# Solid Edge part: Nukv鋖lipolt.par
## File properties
Author: Türk
Template: Iso Part.par
Last saved by: Türk
Revision: 4
Application: Solid Edge
Accuracy: 0,990
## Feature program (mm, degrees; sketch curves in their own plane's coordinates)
thread "unnamed Thread 1"
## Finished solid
Body 1: solid body, 14 faces, 24 edges, 12 vertices.
  Faces by surface: plane 10, cylinder 2, torus 2
  Edges by curve: line 18, circle 6
Bounding box of the edges (mm; curved faces can reach further): 12.700 x 69.700 x 12.700, from (-6.35, 0, -6.35) to (6.35, 69.7, 6.35).
Cylindrical faces by radius (mm): R3 x1, R6.35 x1
Toroidal faces (ring radius, tube radius in mm): R5.85 r0.5 x2
Planar faces by outward normal: +x 1, +y 2, -x 1, -y 2, oblique 4
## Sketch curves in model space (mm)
circle centre (0, 57, 0) radius 3.4641
line (0, 57, 3.4641) -> (3, 57, 1.7321)
line (3, 57, 1.7321) -> (3, 57, -1.7321)
line (3, 57, -1.7321) -> (0, 57, -3.4641)
line (0, 57, -3.4641) -> (-3, 57, -1.7321)
line (-3, 57, -1.7321) -> (-3, 57, 1.7321)
line (-3, 57, 1.7321) -> (0, 57, 3.4641)
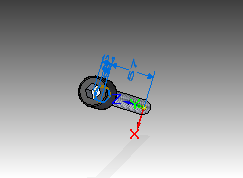
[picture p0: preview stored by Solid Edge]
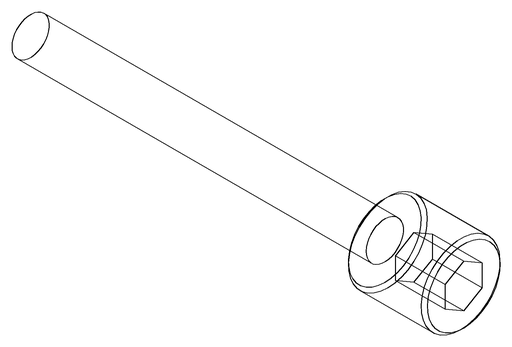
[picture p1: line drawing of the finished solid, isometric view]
